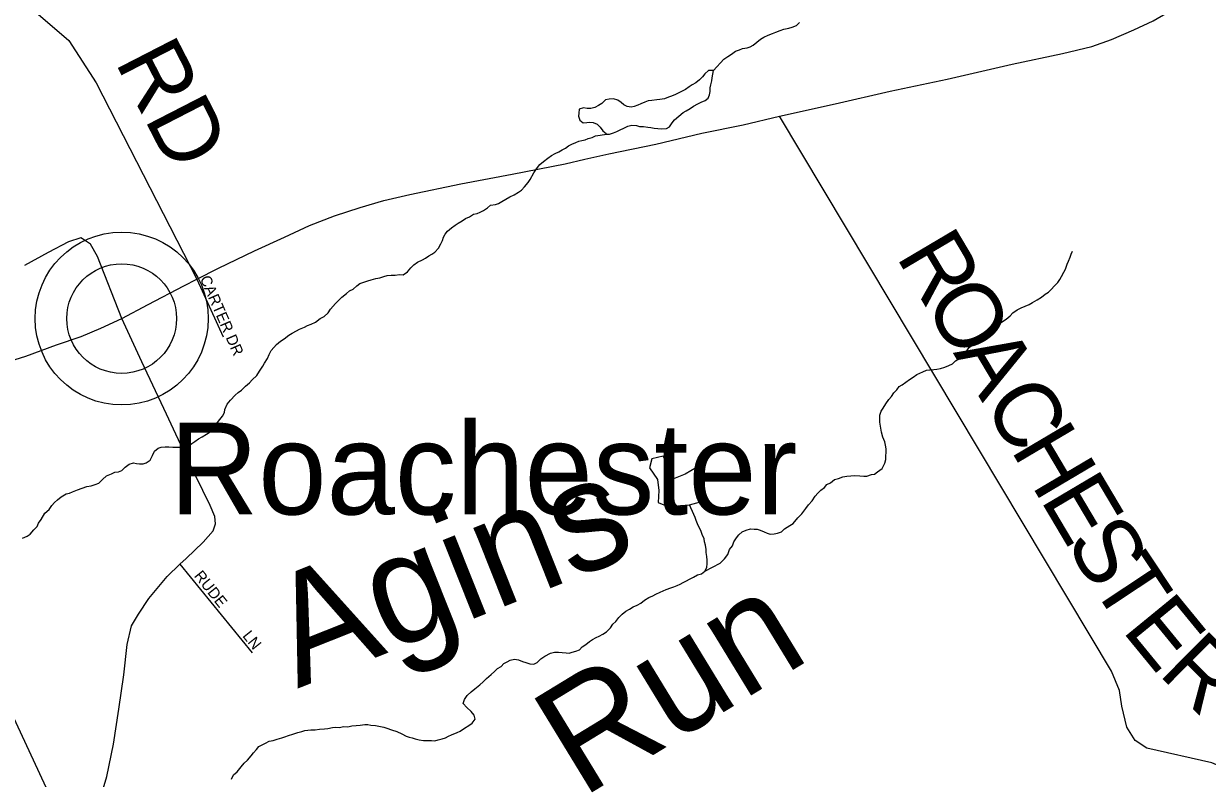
# Model space of a CAD drawing. Extents: x 0 to 1064, y 0 to 440.
# Drawn here: x 334.77 to 351.06, y 145.11 to 155.51 of the extents above; entities that cross this region are included whole.
import ezdxf

# ---------------------------------------------------------------- set-up
doc = ezdxf.new("R2010")
doc.units = 0
for name, color, linetype in [('GM_X_County_Road', 7, 'Continuous'), ('GM_X_County_Road_Text', 7, 'Continuous'), ('GM_X_Minor_Lake', 7, 'Continuous'), ('GM_X_Minor_River', 7, 'Continuous'), ('GM_X_Minor_River_Text', 7, 'Continuous'), ('GM_X_State_Route', 7, 'Continuous'), ('GM_X_Township_Road', 7, 'Continuous'), ('GM_X_Township_Road_Text', 7, 'Continuous'), ('GM_X_Township_Subdivision', 7, 'Continuous'), ('GM_X_Township_Subdivision_Text', 7, 'Continuous'), ('GM_X_Unincorporated', 7, 'Continuous'), ('GM_X_Unincorporated_Location', 7, 'Continuous'), ('GM_X_Unincorporated_Text', 7, 'Continuous'), ('GM_X_US_Route', 7, 'Continuous')]:
    doc.layers.add(name, color=color, linetype=linetype)

msp = doc.modelspace()

# ---------------------------------------------------------------- linework, layer by layer
at = {"layer": 'GM_X_County_Road'}
msp.add_lwpolyline([(354.361, 145.041), (354.206, 145.067), (354.078, 145.026), (353.915, 144.774), (353.558, 144.092), (353.44, 143.936), (353.341, 143.841), (353.17, 143.855), (352.942, 144.041), (351.862, 145.012), (351.124, 145.327), (350.232, 145.529), (350.07, 145.635), (349.957, 145.819), (349.888, 146.106), (349.855, 146.325), (349.744, 146.588), (345.177, 154.237)], dxfattribs=at)
at = {"layer": 'GM_X_Minor_Lake'}
for points in [[(344.266, 154.866), (344.199, 154.862), (344.149, 154.82), (344.118, 154.778), (344.074, 154.737), (344.024, 154.696), (343.975, 154.666), (343.931, 154.637), (343.882, 154.602), (343.789, 154.555), (343.746, 154.532), (343.691, 154.509), (343.648, 154.498), (343.593, 154.475), (343.531, 154.464), (343.489, 154.459), (343.421, 154.449), (343.367, 154.444), (343.323, 154.427), (343.268, 154.404), (343.225, 154.386), (343.176, 154.369), (343.133, 154.358), (343.078, 154.366), (343.036, 154.391), (342.995, 154.422), (342.953, 154.454), (342.892, 154.474), (342.831, 154.469), (342.782, 154.458), (342.733, 154.41), (342.683, 154.381), (342.634, 154.352), (342.579, 154.341), (342.53, 154.342), (342.481, 154.35), (342.42, 154.333), (342.413, 154.278), (342.412, 154.236), (342.429, 154.181), (342.476, 154.143), (342.525, 154.148), (342.568, 154.153), (342.61, 154.146), (342.665, 154.126), (342.706, 154.083), (342.747, 154.033), (342.791, 153.994)], [(342.791, 153.994), (342.795, 153.989), (342.838, 153.988), (342.893, 154.005), (342.936, 154.023), (342.985, 154.046), (343.035, 154.069), (343.09, 154.098), (343.145, 154.109), (343.206, 154.107), (343.248, 154.094), (343.303, 154.093), (343.364, 154.085), (343.406, 154.078), (343.449, 154.071), (343.503, 154.064), (343.558, 154.062), (343.619, 154.067), (343.662, 154.09), (343.7, 154.144), (343.731, 154.186), (343.793, 154.233), (343.85, 154.286), (343.893, 154.31), (343.948, 154.339), (343.992, 154.374), (344.053, 154.403), (344.097, 154.426), (344.152, 154.449), (344.195, 154.485), (344.215, 154.527), (344.222, 154.575), (344.223, 154.624), (344.23, 154.666), (344.244, 154.721), (344.251, 154.763), (344.266, 154.866)], [(343.937, 148.881), (344.091, 148.921), (344.149, 149.078), (344.073, 149.244), (344.034, 149.396), (343.879, 149.302), (343.719, 149.239), (343.655, 149.398), (343.573, 149.552), (343.42, 149.513), (343.387, 149.392)], [(343.387, 149.392), (343.499, 149.231), (343.514, 149.079), (343.505, 148.915), (343.662, 148.851), (343.815, 148.872), (343.937, 148.881)]]:
    msp.add_lwpolyline(points, dxfattribs=at)
at = {"layer": 'GM_X_Minor_River'}
for points in [[(344.266, 154.866), (344.41, 155.021), (344.465, 155.056), (344.515, 155.091), (344.571, 155.132), (344.626, 155.149), (344.669, 155.166), (344.73, 155.177), (344.773, 155.188), (344.816, 155.211), (344.866, 155.253), (344.916, 155.294), (344.959, 155.323), (345.021, 155.352), (345.082, 155.375), (345.125, 155.392), (345.187, 155.415), (345.236, 155.432), (345.303, 155.449), (345.352, 155.46), (345.408, 155.483), (345.451, 155.524)], [(340.517, 152.476), (340.536, 152.524), (340.55, 152.566), (340.575, 152.608), (340.607, 152.65), (340.663, 152.697), (340.712, 152.733), (340.755, 152.762), (340.811, 152.791), (340.854, 152.826), (340.91, 152.849), (340.965, 152.885), (341.014, 152.896), (341.058, 152.913), (341.101, 152.936), (341.156, 152.971), (341.2, 153.007), (341.267, 153.017), (341.31, 153.034), (341.353, 153.058), (341.409, 153.093), (341.465, 153.122), (341.526, 153.151), (341.582, 153.186), (341.625, 153.215), (341.669, 153.263), (341.719, 153.322), (341.745, 153.364), (341.795, 153.454), (341.833, 153.508), (341.877, 153.568), (341.927, 153.609), (341.989, 153.656), (342.039, 153.692), (342.088, 153.721), (342.138, 153.744), (342.187, 153.773), (342.23, 153.796), (342.274, 153.826), (342.317, 153.849), (342.372, 153.872), (342.415, 153.889), (342.458, 153.9), (342.501, 153.911), (342.544, 153.929), (342.599, 153.94), (342.642, 153.963), (342.709, 153.973), (342.795, 153.989)], [(335.642, 149.134), (335.703, 149.145), (335.759, 149.162), (335.808, 149.179), (335.858, 149.232), (335.914, 149.279), (335.981, 149.308), (336.031, 149.331), (336.08, 149.336), (336.123, 149.353), (336.173, 149.401), (336.228, 149.442), (336.284, 149.459), (336.326, 149.452), (336.368, 149.445), (336.417, 149.444), (336.46, 149.461), (336.516, 149.496), (336.548, 149.562), (336.574, 149.622), (336.624, 149.664), (336.666, 149.675), (336.721, 149.679), (336.77, 149.678), (336.825, 149.677), (336.879, 149.676), (336.922, 149.675), (336.965, 149.674), (337.038, 149.69), (337.088, 149.725), (337.131, 149.755), (337.181, 149.79), (337.23, 149.819), (337.292, 149.854), (337.354, 149.895), (337.41, 149.973), (337.473, 150.057), (337.511, 150.104), (337.537, 150.152), (337.544, 150.195), (337.576, 150.267), (337.62, 150.321), (337.683, 150.392), (337.726, 150.427), (337.77, 150.463), (337.826, 150.516), (337.882, 150.563), (337.919, 150.605), (337.982, 150.664), (338.02, 150.724), (338.064, 150.79), (338.089, 150.832), (338.128, 150.898), (338.153, 150.952), (338.179, 151.006), (338.217, 151.048), (338.254, 151.09), (338.31, 151.137), (338.36, 151.166), (338.422, 151.219), (338.471, 151.248), (338.527, 151.277), (338.57, 151.301), (338.638, 151.33), (338.681, 151.353), (338.73, 151.37), (338.792, 151.399), (338.854, 151.446), (338.909, 151.475), (338.965, 151.528), (338.997, 151.576), (339.066, 151.654), (339.109, 151.695), (339.153, 151.743), (339.215, 151.79), (339.259, 151.831), (339.308, 151.854), (339.358, 151.896), (339.401, 151.931), (339.457, 151.948), (339.512, 151.965), (339.555, 151.982), (339.622, 151.999), (339.677, 152.01), (339.733, 152.027), (339.775, 152.038), (339.83, 152.043), (339.885, 152.047), (339.946, 152.052), (339.995, 152.051), (340.057, 152.092), (340.101, 152.145), (340.144, 152.187), (340.194, 152.222), (340.262, 152.257), (340.305, 152.28), (340.348, 152.31), (340.392, 152.333), (340.435, 152.362), (340.485, 152.416), (340.517, 152.476)], [(348.5, 151.596), (348.556, 151.619), (348.611, 151.642), (348.66, 151.666), (348.722, 151.707), (348.784, 151.742), (348.834, 151.783), (348.877, 151.812), (348.921, 151.854), (348.958, 151.895), (349.008, 151.943), (349.033, 151.985), (349.059, 152.027), (349.091, 152.087), (349.11, 152.129), (349.136, 152.195), (349.155, 152.237), (349.175, 152.291), (349.188, 152.334), (349.208, 152.376)], [(344.148, 147.968), (344.358, 148.079), (344.42, 148.138), (344.464, 148.198), (344.49, 148.264), (344.528, 148.318), (344.548, 148.372), (344.586, 148.426), (344.617, 148.468), (344.661, 148.509), (344.716, 148.532), (344.777, 148.549), (344.826, 148.548), (344.869, 148.547), (344.911, 148.534), (344.965, 148.508), (345.007, 148.489), (345.049, 148.476), (345.104, 148.48), (345.147, 148.491), (345.202, 148.508), (345.246, 148.55), (345.32, 148.597), (345.364, 148.626), (345.427, 148.704), (345.483, 148.757), (345.539, 148.829), (345.577, 148.882), (345.627, 148.936), (345.665, 149.002), (345.703, 149.044), (345.747, 149.085), (345.796, 149.12), (345.828, 149.162), (345.877, 149.185), (345.933, 149.232), (345.988, 149.243), (346.049, 149.266), (346.104, 149.277), (346.159, 149.282), (346.214, 149.287), (346.281, 149.279), (346.336, 149.278), (346.378, 149.276), (346.44, 149.299), (346.483, 149.304), (346.526, 149.334), (346.588, 149.381), (346.626, 149.453), (346.64, 149.507), (346.641, 149.55), (346.642, 149.605), (346.643, 149.653), (346.633, 149.702), (346.628, 149.751), (346.599, 149.812), (346.582, 149.88), (346.566, 149.965), (346.555, 150.02), (346.556, 150.063), (346.558, 150.117), (346.577, 150.171), (346.603, 150.213), (346.641, 150.273), (346.679, 150.333), (346.716, 150.375), (346.748, 150.423), (346.792, 150.464), (346.823, 150.512), (346.866, 150.535), (346.966, 150.606), (347.015, 150.641), (347.065, 150.677), (347.108, 150.694), (347.151, 150.711), (347.2, 150.734), (347.243, 150.739), (347.298, 150.744), (347.341, 150.749), (347.39, 150.76), (347.451, 150.777), (347.506, 150.8), (347.555, 150.823), (347.599, 150.864), (347.655, 150.899), (347.711, 150.971), (347.761, 151.012), (347.793, 151.054), (347.861, 151.101), (347.91, 151.136), (347.972, 151.177), (348.01, 151.219), (348.053, 151.242), (348.109, 151.284), (348.183, 151.343), (348.233, 151.396), (348.295, 151.437), (348.351, 151.485), (348.389, 151.526), (348.445, 151.567), (348.5, 151.596)], [(334.76, 148.42), (334.822, 148.449), (334.865, 148.478), (334.915, 148.538), (334.959, 148.585), (334.978, 148.627), (335.016, 148.681), (335.067, 148.765), (335.123, 148.818), (335.161, 148.872), (335.199, 148.914), (335.242, 148.949), (335.292, 148.99), (335.36, 149.031), (335.403, 149.043), (335.446, 149.06), (335.513, 149.088), (335.581, 149.111), (335.642, 149.134)], [(340.879, 146.254), (340.935, 146.307), (340.984, 146.348), (341.053, 146.401), (341.096, 146.443), (341.146, 146.49), (341.208, 146.544), (341.252, 146.585), (341.296, 146.627), (341.345, 146.656), (341.383, 146.698), (341.426, 146.721), (341.469, 146.744), (341.53, 146.755), (341.585, 146.747), (341.639, 146.722), (341.687, 146.708), (341.742, 146.689), (341.796, 146.688), (341.84, 146.711), (341.89, 146.758), (341.945, 146.799), (342.026, 146.84), (342.081, 146.851), (342.135, 146.85), (342.184, 146.848), (342.239, 146.841), (342.281, 146.84), (342.324, 146.851), (342.373, 146.868), (342.422, 146.885), (342.46, 146.927), (342.509, 146.956), (342.559, 146.997), (342.602, 147.027), (342.652, 147.056), (342.695, 147.073), (342.744, 147.102), (342.794, 147.132), (342.85, 147.185), (342.882, 147.239), (342.925, 147.274), (342.963, 147.328), (343.013, 147.376), (343.063, 147.417), (343.112, 147.446), (343.162, 147.475), (343.217, 147.498), (343.266, 147.528), (343.316, 147.569), (343.378, 147.604), (343.433, 147.627), (343.476, 147.65), (343.532, 147.679), (343.575, 147.696), (343.618, 147.714), (343.679, 147.736), (343.723, 147.754), (343.766, 147.771), (343.809, 147.788), (343.852, 147.811), (343.895, 147.835), (343.938, 147.858), (343.994, 147.887), (344.049, 147.916), (344.104, 147.933), (344.148, 147.968), (344.174, 148.016), (344.181, 148.071), (344.182, 148.12), (344.177, 148.168), (344.166, 148.223), (344.168, 148.266), (344.157, 148.327), (344.146, 148.37), (344.141, 148.412), (344.112, 148.474), (344.095, 148.529), (344.066, 148.578), (344.049, 148.621), (344.031, 148.664), (344.014, 148.707), (343.997, 148.75), (343.937, 148.881)], [(337.636, 145.104), (337.661, 145.164), (337.711, 145.205), (337.768, 145.271), (337.811, 145.324), (337.855, 145.366), (337.905, 145.426), (337.937, 145.467), (337.98, 145.509), (338.012, 145.551), (338.055, 145.574), (338.104, 145.597), (338.154, 145.626), (338.209, 145.637), (338.264, 145.654), (338.325, 145.671), (338.368, 145.688), (338.418, 145.705), (338.479, 145.722), (338.546, 145.744), (338.602, 145.761), (338.645, 145.773), (338.724, 145.783), (338.785, 145.781), (338.846, 145.792), (338.913, 145.796), (338.962, 145.801), (339.023, 145.812), (339.072, 145.817), (339.114, 145.816), (339.182, 145.826), (339.236, 145.825), (339.291, 145.836), (339.352, 145.841), (339.407, 145.845), (339.468, 145.856), (339.511, 145.855), (339.553, 145.848), (339.614, 145.84), (339.687, 145.826), (339.729, 145.819), (339.772, 145.806), (339.838, 145.78), (339.91, 145.76), (339.977, 145.728), (340.037, 145.696), (340.079, 145.683), (340.121, 145.67), (340.164, 145.657), (340.218, 145.643), (340.279, 145.636), (340.34, 145.634), (340.388, 145.633), (340.431, 145.632), (340.48, 145.643), (340.535, 145.66), (340.578, 145.671), (340.621, 145.694), (340.664, 145.712), (340.738, 145.746), (340.781, 145.764), (340.843, 145.805), (340.899, 145.84), (340.948, 145.875), (340.986, 145.929), (340.975, 145.984), (340.934, 146.034), (340.874, 146.09), (340.821, 146.146), (340.841, 146.2), (340.879, 146.254)]]:
    msp.add_lwpolyline(points, dxfattribs=at)
at = {"layer": 'GM_X_State_Route'}
msp.add_lwpolyline([(335.785, 144.693), (335.919, 145.139), (336.011, 145.587), (336.086, 146.065), (336.154, 146.538), (336.197, 146.956), (336.259, 147.216), (336.355, 147.377), (336.495, 147.592), (336.748, 147.895), (336.925, 148.062), (337.012, 148.144), (337.244, 148.368), (337.382, 148.522), (337.416, 148.619), (337.406, 148.722), (337.343, 148.87), (337.032, 149.499), (336.738, 150.128), (336.399, 150.849), (336.123, 151.447)], dxfattribs=at)
at = {"layer": 'GM_X_Township_Road'}
msp.add_lwpolyline([(331.597, 158.436), (331.729, 158.236), (331.979, 158.112), (332.73, 157.653), (333.524, 156.938), (334.813, 155.778), (335.396, 155.278), (335.771, 154.694), (337.156, 151.988)], dxfattribs=at)
at = {"layer": 'GM_X_Township_Subdivision'}
for points in [[(335.582, 152.547), (335.561, 152.561), (335.392, 152.504), (335.111, 152.357), (334.785, 152.18)], [(336.123, 151.447), (335.789, 152.3), (335.694, 152.474), (335.582, 152.547)], [(337.156, 151.988), (337.521, 151.196)], [(335.561, 143.959), (333.922, 147.481), (332.545, 150.442)], [(336.925, 148.062), (337.921, 146.845)]]:
    msp.add_lwpolyline(points, dxfattribs=at)
at = {"layer": 'GM_X_Unincorporated'}
for radius in [1.19, 0.755]:
    msp.add_circle((336.123, 151.447), radius, dxfattribs=at)
at = {"layer": 'GM_X_Unincorporated_Location'}
msp.add_line((336.123, 151.447), (336.123, 151.447), dxfattribs=at)
at = {"layer": 'GM_X_US_Route'}
for points in [[(342.495, 153.641), (342.827, 153.715), (343.472, 153.85), (344.105, 154.002), (344.676, 154.114), (345.177, 154.237), (345.941, 154.406), (346.697, 154.58), (347.483, 154.746), (348.38, 154.952), (349.073, 155.097), (349.473, 155.195), (349.744, 155.291), (350.053, 155.422), (350.319, 155.549), (350.66, 155.746), (351.176, 156.066)], [(334.525, 150.841), (334.802, 150.93), (335.228, 151.083), (335.566, 151.201), (335.838, 151.315), (336.123, 151.447), (336.488, 151.643), (336.978, 151.897), (337.156, 151.988), (337.455, 152.139), (337.95, 152.381), (338.364, 152.57), (338.71, 152.73), (339.05, 152.861), (339.407, 152.978), (339.733, 153.073), (340.089, 153.154), (340.789, 153.304), (341.495, 153.437), (342.225, 153.58), (342.495, 153.641)]]:
    msp.add_lwpolyline(points, dxfattribs=at)

# ---------------------------------------------------------------- texts
at = {"layer": 'GM_X_County_Road_Text'}
for s, rotation, p in [('R', 300.6432, (346.772, 152.306)), ('O', 300.6432, (347.152, 151.664)), ('A', 300.6432, (347.56, 150.976)), ('C', 300.6432, (347.968, 150.287)), ('H', 300.6432, (348.348, 149.645)), ('E', 300.6432, (348.756, 148.957)), ('S', 300.6432, (349.103, 148.372)), ('T', 303.5384, (349.442, 147.802)), ('E', 309.3288, (349.877, 147.154)), ('R', 315.1191, (350.376, 146.554))]:
    msp.add_text(s, height=0.909, rotation=rotation, dxfattribs=at).set_placement(p)
at = {"layer": 'GM_X_Minor_River_Text'}
for s, rotation, p in [('Agins', 21.6815, (338.543, 146.349)), ('Run', 31.3682, (342.454, 144.834))]:
    msp.add_text(s, height=1.5152, rotation=rotation, dxfattribs=at).set_placement(p)
at = {"layer": 'GM_X_Township_Road_Text'}
msp.add_text('RD', height=0.9091, rotation=297.2273, dxfattribs=at).set_placement((336.024, 154.987))
at = {"layer": 'GM_X_Township_Subdivision_Text'}
for s, rotation, p in [('CARTER DR', 293.585, (337.196, 152.001)), ('RUDE', 308.6589, (337.112, 147.901)), ('LN', 308.6634, (337.778, 147.074))]:
    msp.add_text(s, height=0.1515, rotation=rotation, dxfattribs=at).set_placement(p)
at = {"layer": 'GM_X_Unincorporated_Text'}
msp.add_text('Roachester', height=1.2636, rotation=0, dxfattribs=at).set_placement((336.783, 148.749))

doc.saveas('drawing.dxf')
